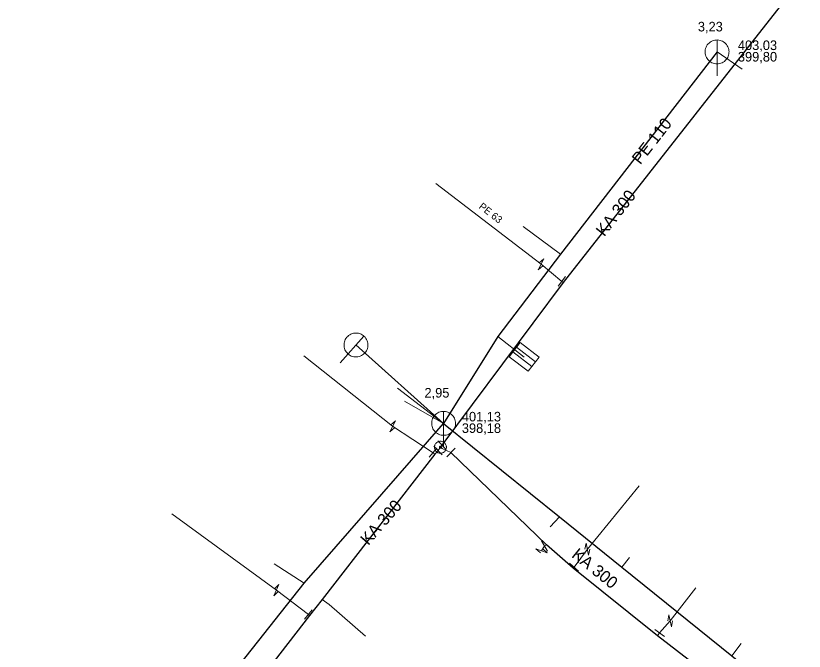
# Model space of a CAD drawing. Extents: x -809028 to -807737, y -990545 to -989489.
# Drawn here: x -808675 to -808609.2, y -989928.5 to -989875.5 of the extents above; entities that cross this region are included whole.
import ezdxf

# ---------------------------------------------------------------- set-up
doc = ezdxf.new("R2010")
doc.units = 0
doc.header["$LTSCALE"] = 0.32
for name, color, linetype, lineweight in [('1', 7, 'Continuous', 13), ('11', 7, 'Continuous', 13), ('13', 7, 'Continuous', 13), ('14', 7, 'Continuous', 25), ('17', 7, 'Continuous', 25), ('22', 7, 'Continuous', 13), ('34', 7, 'Continuous', 13), ('47', 7, 'Continuous', 13)]:
    doc.layers.add(name, color=color, linetype=linetype, lineweight=lineweight)

msp = doc.modelspace()

# ---------------------------------------------------------------- linework, layer by layer
at = {"layer": '11'}
for p, q in [((-808614.34, -989879.949), (-808616.449, -989878.52)), ((-808632.649, -989893.09), (-808629.51, -989895.41)), ((-808632.549, -989903.979), (-808634.761, -989902.278)), ((-808646.601, -989902.976), (-808639.281, -989909.515)), ((-808643.14, -989906.59), (-808639.281, -989909.515)), ((-808642.539, -989907.66), (-808639.281, -989909.515)), ((-808630.386, -989918.155), (-808629.598, -989917.322)), ((-808623.75, -989920.717), (-808624.403, -989921.511)), ((-808653.44, -989921.23), (-808650.917, -989922.864)), ((-808614.441, -989927.888), (-808615.221, -989928.912))]:
    msp.add_line(p, q, dxfattribs=at)
at = {"layer": '13'}
for p, q in [((-808627.278, -989920.008), (-808622.951, -989914.734)), ((-808630.856, -989919.743), (-808631.102, -989920.158)), ((-808628.389, -989921.509), (-808627.278, -989920.008)), ((-808618.23, -989923.232), (-808620.363, -989925.999)), ((-808621.246, -989927.006), (-808620.363, -989925.999))]:
    msp.add_line(p, q, dxfattribs=at)
for points in [[(-808629.41, -989897.67), (-808631.149, -989896.239), (-808639.923, -989889.493)], [(-808640.16, -989911.969), (-808643.539, -989909.759), (-808650.952, -989903.868)], [(-808650.579, -989925.47), (-808653.249, -989923.439), (-808661.973, -989917.059)], [(-808649.42, -989924.206), (-808648.851, -989924.64), (-808645.792, -989927.276)]]:
    msp.add_lwpolyline(points, dxfattribs=at)
at = {"layer": '14', "lineweight": 13}
for p, q in [((-808629.289, -989897.76), (-808629.41, -989897.67)), ((-808639.749, -989911.778), (-808639.549, -989911.509)), ((-808639.429, -989911.329), (-808639.549, -989911.509)), ((-808640.004, -989912.101), (-808640.16, -989911.97)), ((-808630.686, -989919.647), (-808630.856, -989919.743)), ((-808628.477, -989921.605), (-808628.389, -989921.509)), ((-808650.469, -989925.559), (-808650.579, -989925.47)), ((-808621.423, -989927.259), (-808621.246, -989927.006))]:
    msp.add_line(p, q, dxfattribs=at)
at = {"layer": '14'}
for points in [[(-808616.449, -989878.52), (-808629.51, -989895.41), (-808634.761, -989902.278), (-808639.281, -989909.515)], [(-808659.149, -989933.219), (-808650.917, -989922.864), (-808639.281, -989909.515)], [(-808639.281, -989909.515), (-808629.598, -989917.322), (-808624.403, -989921.511), (-808615.221, -989928.912), (-808610.879, -989932.412)]]:
    msp.add_lwpolyline(points, dxfattribs=at)
at = {"layer": '14', "lineweight": 13}
msp.add_lwpolyline([(-808638.669, -989911.952), (-808639.399, -989911.609), (-808639.549, -989911.509)], dxfattribs=at)
at = {"layer": '17'}
for points in [[(-808611.169, -989874.699), (-808629.289, -989897.76), (-808639.429, -989911.329)], [(-808639.749, -989911.778), (-808640.004, -989912.101), (-808649.42, -989924.206), (-808650.469, -989925.559), (-808660.48, -989938.469), (-808670.67, -989951.699), (-808677.579, -989961.079), (-808683.539, -989969.399), (-808691.52, -989986.17), (-808694.273, -989996.242)], [(-808600.013, -989988.618), (-808601.767, -989983.94), (-808603.874, -989980.796), (-808595.03, -989969.311), (-808584.982, -989956.438), (-808593.302, -989949.39), (-808594.743, -989947.892), (-808605.238, -989940.263), (-808609.713, -989936.474), (-808615.675, -989931.666), (-808621.423, -989927.259), (-808628.477, -989921.605), (-808630.686, -989919.647), (-808638.669, -989911.952)]]:
    msp.add_lwpolyline(points, dxfattribs=at)
at = {"layer": '22'}
for p, q in [((-808616.449, -989880.52), (-808616.448, -989877.52)), ((-808647.933, -989904.467), (-808645.935, -989902.23)), ((-808633.498, -989903.555), (-808631.913, -989904.775)), ((-808633.193, -989903.159), (-808631.608, -989904.378)), ((-808639.281, -989911.515), (-808639.28, -989908.515))]:
    msp.add_line(p, q, dxfattribs=at)
for points in [[(-808615.449, -989878.52), (-808615.454, -989878.411), (-808615.472, -989878.303), (-808615.502, -989878.197), (-808615.542, -989878.096), (-808615.594, -989877.999), (-808615.656, -989877.909), (-808615.728, -989877.826), (-808615.808, -989877.752), (-808615.896, -989877.686), (-808615.99, -989877.631), (-808616.09, -989877.586), (-808616.195, -989877.553), (-808616.302, -989877.531), (-808616.411, -989877.521), (-808616.521, -989877.523), (-808616.629, -989877.537), (-808616.736, -989877.562), (-808616.839, -989877.599), (-808616.937, -989877.648), (-808617.029, -989877.706), (-808617.115, -989877.775), (-808617.192, -989877.852), (-808617.261, -989877.938), (-808617.32, -989878.03), (-808617.368, -989878.128), (-808617.405, -989878.231), (-808617.431, -989878.338), (-808617.445, -989878.446), (-808617.448, -989878.556), (-808617.438, -989878.665), (-808617.417, -989878.772), (-808617.383, -989878.876), (-808617.339, -989878.976), (-808617.284, -989879.071), (-808617.218, -989879.159), (-808617.144, -989879.239), (-808617.061, -989879.311), (-808616.971, -989879.373), (-808616.875, -989879.425), (-808616.773, -989879.466), (-808616.668, -989879.496), (-808616.56, -989879.514), (-808616.45, -989879.52), (-808616.341, -989879.514), (-808616.233, -989879.496), (-808616.128, -989879.467), (-808616.026, -989879.426), (-808615.929, -989879.374), (-808615.839, -989879.312), (-808615.756, -989879.241), (-808615.681, -989879.161), (-808615.616, -989879.073), (-808615.56, -989878.979), (-808615.516, -989878.879), (-808615.482, -989878.775), (-808615.46, -989878.667), (-808615.45, -989878.558)], [(-808645.855, -989903.642), (-808645.787, -989903.557), (-808645.728, -989903.464), (-808645.68, -989903.365), (-808645.643, -989903.263), (-808645.617, -989903.156), (-808645.603, -989903.048), (-808645.602, -989902.938), (-808645.612, -989902.83), (-808645.634, -989902.722), (-808645.667, -989902.618), (-808645.712, -989902.518), (-808645.768, -989902.423), (-808645.833, -989902.336), (-808645.908, -989902.256), (-808645.991, -989902.184), (-808646.081, -989902.122), (-808646.177, -989902.07), (-808646.279, -989902.029), (-808646.385, -989902), (-808646.492, -989901.982), (-808646.602, -989901.976), (-808646.711, -989901.982), (-808646.819, -989902), (-808646.925, -989902.029), (-808647.026, -989902.071), (-808647.122, -989902.123), (-808647.213, -989902.185), (-808647.295, -989902.256), (-808647.37, -989902.337), (-808647.435, -989902.425), (-808647.491, -989902.519), (-808647.535, -989902.619), (-808647.568, -989902.723), (-808647.591, -989902.83), (-808647.6, -989902.94), (-808647.598, -989903.049), (-808647.584, -989903.158), (-808647.558, -989903.264), (-808647.521, -989903.367), (-808647.473, -989903.465), (-808647.414, -989903.558), (-808647.346, -989903.643), (-808647.268, -989903.721), (-808647.183, -989903.789), (-808647.09, -989903.848), (-808646.992, -989903.896), (-808646.889, -989903.933), (-808646.782, -989903.959), (-808646.674, -989903.973), (-808646.564, -989903.975), (-808646.455, -989903.966), (-808646.348, -989903.943), (-808646.244, -989903.91), (-808646.144, -989903.865), (-808646.05, -989903.81), (-808645.961, -989903.744), (-808645.881, -989903.67)], [(-808632.888, -989902.762), (-808631.303, -989903.982), (-808632.218, -989905.171), (-808633.803, -989903.951)], [(-808638.281, -989909.515), (-808638.286, -989909.406), (-808638.304, -989909.298), (-808638.334, -989909.192), (-808638.374, -989909.091), (-808638.426, -989908.994), (-808638.488, -989908.904), (-808638.56, -989908.821), (-808638.64, -989908.747), (-808638.728, -989908.681), (-808638.822, -989908.626), (-808638.922, -989908.581), (-808639.027, -989908.548), (-808639.134, -989908.526), (-808639.243, -989908.516), (-808639.353, -989908.518), (-808639.461, -989908.532), (-808639.568, -989908.557), (-808639.671, -989908.594), (-808639.769, -989908.643), (-808639.861, -989908.701), (-808639.947, -989908.77), (-808640.024, -989908.847), (-808640.093, -989908.933), (-808640.152, -989909.025), (-808640.2, -989909.123), (-808640.237, -989909.226), (-808640.263, -989909.333), (-808640.277, -989909.441), (-808640.28, -989909.551), (-808640.27, -989909.66), (-808640.249, -989909.767), (-808640.215, -989909.871), (-808640.171, -989909.971), (-808640.116, -989910.066), (-808640.05, -989910.154), (-808639.976, -989910.234), (-808639.893, -989910.306), (-808639.803, -989910.368), (-808639.707, -989910.42), (-808639.605, -989910.461), (-808639.5, -989910.491), (-808639.392, -989910.509), (-808639.282, -989910.515), (-808639.173, -989910.509), (-808639.065, -989910.491), (-808638.96, -989910.462), (-808638.858, -989910.421), (-808638.761, -989910.369), (-808638.671, -989910.307), (-808638.588, -989910.236), (-808638.513, -989910.156), (-808638.448, -989910.068), (-808638.392, -989909.974), (-808638.348, -989909.874), (-808638.314, -989909.77), (-808638.292, -989909.662), (-808638.282, -989909.553)]]:
    msp.add_lwpolyline(points, close=True, dxfattribs=at)
at = {"layer": '34'}
for p, q in [((-808629.111, -989897.268), (-808629.708, -989898.07)), ((-808639.775, -989910.968), (-808639.082, -989911.689)), ((-808639.838, -989911.585), (-808640.481, -989912.351)), ((-808640.095, -989911.417), (-808639.402, -989912.138)), ((-808638.322, -989911.591), (-808639.016, -989912.311)), ((-808631.103, -989919.308), (-808630.609, -989920.178)), ((-808628.758, -989921.171), (-808628.02, -989921.847)), ((-808650.262, -989925.082), (-808650.896, -989925.856)), ((-808621.656, -989926.72), (-808620.836, -989927.292))]:
    msp.add_line(p, q, dxfattribs=at)
at = {"layer": '47'}
for p, q in [((-808630.921, -989895.782), (-808631.308, -989896.116)), ((-808643.304, -989909.306), (-808643.696, -989909.633)), ((-808627.376, -989919.508), (-808627.479, -989920.008)), ((-808631.582, -989919.987), (-808631.204, -989920.33)), ((-808653.032, -989922.977), (-808653.411, -989923.32)), ((-808620.461, -989925.499), (-808620.564, -989925.999))]:
    msp.add_line(p, q, dxfattribs=at)
for points in [[(-808630.921, -989895.782), (-808631.376, -989896.695), (-808630.989, -989896.361)], [(-808643.304, -989909.306), (-808643.773, -989910.211), (-808643.381, -989909.884)], [(-808627.376, -989919.508), (-808627.18, -989920.508), (-808627.077, -989920.008)], [(-808631.582, -989919.987), (-808630.621, -989920.328), (-808630.999, -989919.985)], [(-808653.032, -989922.977), (-808653.465, -989923.9), (-808653.086, -989923.557)], [(-808620.461, -989925.499), (-808620.265, -989926.499), (-808620.162, -989925.999)]]:
    msp.add_lwpolyline(points, dxfattribs=at)
for points in [[(-808639.251, -989911.107), (-808639.295, -989911.078), (-808639.341, -989911.054), (-808639.39, -989911.035), (-808639.44, -989911.02), (-808639.492, -989911.012), (-808639.545, -989911.009), (-808639.596, -989911.012), (-808639.648, -989911.019), (-808639.698, -989911.032), (-808639.748, -989911.05), (-808639.795, -989911.074), (-808639.839, -989911.102), (-808639.88, -989911.134), (-808639.917, -989911.171), (-808639.95, -989911.211), (-808639.979, -989911.255), (-808640.003, -989911.301), (-808640.023, -989911.351), (-808640.037, -989911.4), (-808640.045, -989911.452), (-808640.048, -989911.505), (-808640.046, -989911.557), (-808640.038, -989911.609), (-808640.026, -989911.659), (-808640.007, -989911.708), (-808639.983, -989911.755), (-808639.955, -989911.8), (-808639.923, -989911.84), (-808639.886, -989911.877), (-808639.846, -989911.91), (-808639.802, -989911.939), (-808639.756, -989911.963), (-808639.707, -989911.983), (-808639.657, -989911.997), (-808639.605, -989912.005), (-808639.553, -989912.009), (-808639.5, -989912.007), (-808639.449, -989911.999), (-808639.398, -989911.986), (-808639.349, -989911.967), (-808639.302, -989911.943), (-808639.258, -989911.916), (-808639.217, -989911.883), (-808639.18, -989911.846), (-808639.147, -989911.806), (-808639.118, -989911.762), (-808639.094, -989911.716), (-808639.074, -989911.668), (-808639.06, -989911.617), (-808639.052, -989911.565), (-808639.048, -989911.513), (-808639.051, -989911.461), (-808639.059, -989911.409), (-808639.072, -989911.359), (-808639.09, -989911.309), (-808639.114, -989911.262), (-808639.141, -989911.219), (-808639.174, -989911.177), (-808639.211, -989911.14)], [(-808639.5, -989911.443), (-808639.507, -989911.437), (-808639.515, -989911.434), (-808639.522, -989911.431), (-808639.53, -989911.429), (-808639.539, -989911.427), (-808639.548, -989911.427), (-808639.556, -989911.427), (-808639.565, -989911.428), (-808639.573, -989911.431), (-808639.581, -989911.433), (-808639.589, -989911.437), (-808639.596, -989911.442), (-808639.603, -989911.447), (-808639.609, -989911.452), (-808639.614, -989911.46), (-808639.62, -989911.467), (-808639.623, -989911.475), (-808639.626, -989911.482), (-808639.628, -989911.49), (-808639.63, -989911.499), (-808639.63, -989911.508), (-808639.63, -989911.516), (-808639.629, -989911.525), (-808639.627, -989911.534), (-808639.624, -989911.541), (-808639.62, -989911.549), (-808639.615, -989911.556), (-808639.61, -989911.563), (-808639.605, -989911.569), (-808639.597, -989911.574), (-808639.59, -989911.58), (-808639.582, -989911.583), (-808639.575, -989911.586), (-808639.567, -989911.588), (-808639.558, -989911.59), (-808639.55, -989911.591), (-808639.541, -989911.59), (-808639.532, -989911.589), (-808639.523, -989911.587), (-808639.516, -989911.584), (-808639.508, -989911.58), (-808639.501, -989911.575), (-808639.494, -989911.57), (-808639.488, -989911.565), (-808639.483, -989911.557), (-808639.477, -989911.55), (-808639.474, -989911.542), (-808639.471, -989911.535), (-808639.469, -989911.527), (-808639.467, -989911.518), (-808639.466, -989911.51), (-808639.467, -989911.501), (-808639.468, -989911.492), (-808639.471, -989911.484), (-808639.473, -989911.476), (-808639.477, -989911.468), (-808639.482, -989911.461), (-808639.487, -989911.454), (-808639.492, -989911.448)]]:
    msp.add_lwpolyline(points, close=True, dxfattribs=at)

# ---------------------------------------------------------------- texts
at = {"layer": '1'}
for s, p in [('3,23', (-808618.049, -989876.808)), ('2,95', (-808640.88, -989907.363))]:
    msp.add_text(s, height=0.8, dxfattribs=at).set_placement(p)
for s, height, rotation, p in [('PE 110', 1, 52, (-808622.857, -989887.979)), ('KA 300', 1, 52, (-808625.864, -989893.986)), ('PE 63 ', 0.6, 322, (-808636.395, -989891.522)), ('KA 300', 1, 49, (-808645.573, -989919.755)), ('KA 300', 1, 321, (-808628.661, -989920.627))]:
    msp.add_text(s, height=height, rotation=rotation, dxfattribs=at).set_placement(p)
at = {"layer": '14'}
for s, p in [('403,03', (-808614.707, -989878.36)), ('399,80', (-808614.707, -989879.32)), ('401,13', (-808637.759, -989909.356)), ('398,18', (-808637.759, -989910.316))]:
    msp.add_text(s, height=0.8, dxfattribs=at).set_placement(p)

doc.saveas('drawing.dxf')
